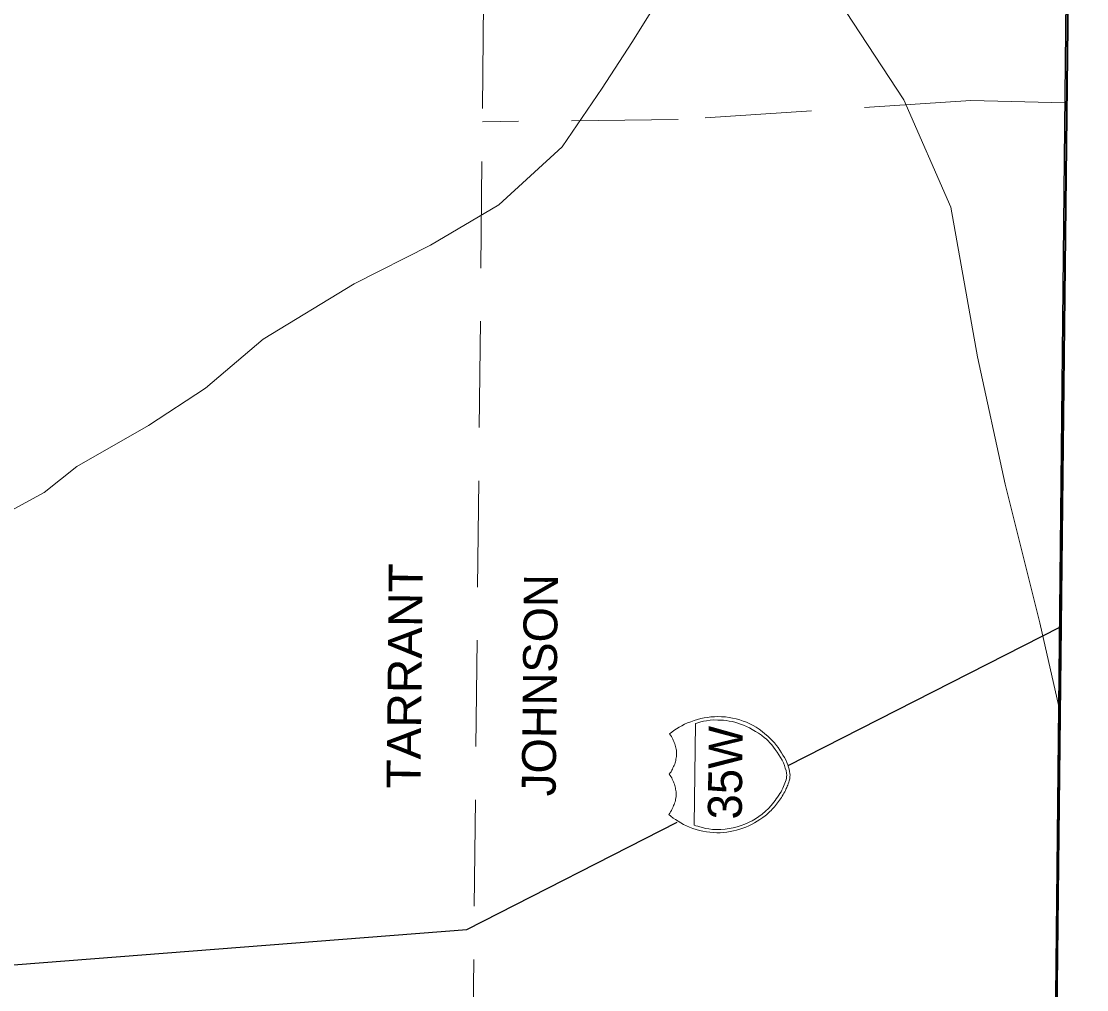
# Model space of a CAD drawing. Extents: x 2356576 to 2377878, y 6966390 to 6990634.
# Drawn here: x 2366013.1 to 2366226.3, y 6968926.1 to 6969120 of the extents above; entities that cross this region are included whole.
import ezdxf

# ---------------------------------------------------------------- set-up
doc = ezdxf.new("R2010")
doc.units = 0
doc.header["$LTSCALE"] = 7.1
doc.linetypes.add('MEDIUM_DASHED', pattern=[4.5, 3, -1.5])
doc.layers.add('19', color=7, linetype='Continuous', lineweight=13)
doc.layers.add('8', color=7, linetype='Continuous', lineweight=13)

msp = doc.modelspace()

# ---------------------------------------------------------------- linework, layer by layer
at = {"layer": '19', "lineweight": 35}
msp.add_line((2366217.375, 6968654.072), (2366226.339, 6969461.286), dxfattribs=at)
at = {"layer": '19', "linetype": 'MEDIUM_DASHED'}
msp.add_line((2366100.797, 6968655.28), (2366107.007, 6969254.676), dxfattribs=at)
at = {"layer": '19', "lineweight": 25}
msp.add_line((2366166.623, 6968971.011), (2366220.945, 6968998.678), dxfattribs=at)
for points in [[(2365597.072, 6968660.498), (2366217.375, 6968654.072), (2366223.585, 6969253.468), (2365603.282, 6969259.894)], [(2365867.731, 6968930.001), (2365932.844, 6968930.618), (2366007.222, 6968930.748), (2366102.256, 6968938.164), (2366144.393, 6968959.656)]]:
    msp.add_lwpolyline(points, dxfattribs=at)
at = {"layer": '19'}
for points in [[(2366057.323, 6969199.743), (2366069.126, 6969192.209), (2366091.194, 6969179.379), (2366116.101, 6969171.021), (2366135.168, 6969166.623), (2366152.425, 6969144.183), (2366165.834, 6969143.864), (2366178.148, 6969121.955), (2366189.725, 6969104.283), (2366199.135, 6969082.764), (2366204.465, 6969052.823), (2366210.021, 6969027.324), (2366216.934, 6968999.531), (2366220.78, 6968982.778)], [(2366155.514, 6969175.953), (2366151.383, 6969165.227), (2366148.79, 6969152.413), (2366143.811, 6969129.392), (2366135.33, 6969115.799), (2366129.355, 6969106.648), (2366121.344, 6969094.85), (2366108.711, 6969083.249), (2366095.035, 6969075.202), (2366079.714, 6969067.44), (2366061.538, 6969056.344), (2366050.004, 6969046.563), (2366038.586, 6969039.093), (2366024.252, 6969030.869), (2366017.685, 6969025.629), (2366000.609, 6969016.381)], [(2366143.422, 6968970.259), (2366143.545, 6968970.498), (2366143.668, 6968970.765), (2366143.762, 6968970.976), (2366143.885, 6968971.246), (2366143.947, 6968971.514), (2366144.038, 6968971.753), (2366144.1, 6968971.992), (2366144.135, 6968972.264), (2366144.198, 6968972.503), (2366144.261, 6968972.77), (2366144.263, 6968973.01), (2366144.266, 6968973.282), (2366144.268, 6968973.522), (2366144.271, 6968973.762), (2366144.214, 6968974.063), (2366144.156, 6968974.272), (2366144.127, 6968974.512), (2366144.069, 6968974.785), (2366143.984, 6968975.053), (2366143.927, 6968975.294), (2366143.809, 6968975.567), (2366143.72, 6968975.808), (2366143.602, 6968976.049), (2366143.485, 6968976.291), (2366143.367, 6968976.532), (2366143.222, 6968976.801), (2366143.045, 6968977.075), (2366142.868, 6968977.317), (2366143.291, 6968977.673), (2366143.743, 6968977.996), (2366144.226, 6968978.323), (2366144.769, 6968978.646), (2366145.284, 6968978.94), (2366145.856, 6968979.234), (2366146.458, 6968979.5), (2366147.093, 6968979.762), (2366147.756, 6968979.995), (2366148.418, 6968980.2), (2366149.108, 6968980.373), (2366149.769, 6968980.514), (2366150.462, 6968980.627), (2366151.151, 6968980.74), (2366151.844, 6968980.764), (2366152.532, 6968980.817), (2366153.284, 6968980.749), (2366154.031, 6968980.71), (2366154.782, 6968980.582), (2366155.473, 6968980.487), (2366156.192, 6968980.359), (2366156.909, 6968980.112), (2366157.595, 6968979.893), (2366158.252, 6968979.646), (2366158.909, 6968979.339), (2366159.566, 6968979.004), (2366160.162, 6968978.638), (2366160.79, 6968978.272), (2366161.386, 6968977.813), (2366161.949, 6968977.36), (2366162.516, 6968976.874), (2366163.05, 6968976.328), (2366163.466, 6968975.932), (2366163.85, 6968975.508), (2366164.237, 6968975.024), (2366164.592, 6968974.572), (2366164.915, 6968974.057), (2366165.242, 6968973.545), (2366165.537, 6968973.062), (2366165.832, 6968972.579), (2366166.095, 6968972.096), (2366166.302, 6968971.614), (2366166.505, 6968971.132), (2366166.68, 6968970.646), (2366166.795, 6968970.225), (2366166.883, 6968969.804), (2366166.939, 6968969.383), (2366166.963, 6968969.023)], [(2366166.963, 6968969.023), (2366166.932, 6968968.783), (2366166.93, 6968968.575), (2366166.896, 6968968.336), (2366166.834, 6968968.124), (2366166.771, 6968967.885), (2366166.709, 6968967.646), (2366166.618, 6968967.347), (2366166.523, 6968967.08), (2366166.4, 6968966.841), (2366166.309, 6968966.57), (2366166.154, 6968966.271), (2366166.032, 6968966.005), (2366165.908, 6968965.706), (2366165.758, 6968965.467), (2366165.575, 6968965.169), (2366165.42, 6968964.871), (2366165.237, 6968964.601), (2366165.054, 6968964.303), (2366164.843, 6968964.037), (2366164.66, 6968963.767), (2366164.478, 6968963.501), (2366164.235, 6968963.231), (2366164.052, 6968962.965), (2366163.838, 6968962.727), (2366163.595, 6968962.458), (2366163.384, 6968962.22), (2366163.17, 6968961.982), (2366162.928, 6968961.777), (2366162.685, 6968961.507), (2366162.475, 6968961.301), (2366162.233, 6968961.124), (2366161.991, 6968960.914), (2366161.507, 6968960.559), (2366160.931, 6968960.177), (2366160.388, 6968959.851), (2366159.844, 6968959.528), (2366159.273, 6968959.202), (2366158.698, 6968958.908), (2366158.127, 6968958.646), (2366157.525, 6968958.44), (2366156.922, 6968958.207), (2366156.288, 6968958.005), (2366155.627, 6968957.892), (2366154.997, 6968957.746), (2366154.336, 6968957.605), (2366153.703, 6968957.552), (2366152.983, 6968957.499), (2366152.29, 6968957.474), (2366151.603, 6968957.542), (2366150.912, 6968957.609), (2366150.225, 6968957.708), (2366149.534, 6968957.835), (2366148.876, 6968957.99), (2366148.19, 6968958.177), (2366147.532, 6968958.396), (2366146.874, 6968958.611), (2366146.245, 6968958.917), (2366145.648, 6968959.195), (2366145.083, 6968959.501), (2366144.574, 6968959.807), (2366144.038, 6968960.172), (2366143.561, 6968960.445), (2366143.117, 6968960.81), (2366142.7, 6968961.174), (2366142.883, 6968961.412), (2366143.066, 6968961.682), (2366143.216, 6968961.949), (2366143.339, 6968962.187), (2366143.462, 6968962.458), (2366143.584, 6968962.697), (2366143.679, 6968962.964), (2366143.801, 6968963.203), (2366143.864, 6968963.442), (2366143.954, 6968963.681), (2366144.017, 6968963.953), (2366144.052, 6968964.192), (2366144.115, 6968964.492), (2366144.177, 6968964.699), (2366144.179, 6968964.939), (2366144.182, 6968965.239), (2366144.185, 6968965.479), (2366144.187, 6968965.719), (2366144.13, 6968965.991), (2366144.073, 6968966.232), (2366144.043, 6968966.472), (2366143.986, 6968966.713), (2366143.901, 6968967.014), (2366143.843, 6968967.255), (2366143.726, 6968967.496), (2366143.636, 6968967.737), (2366143.519, 6968968.006), (2366143.402, 6968968.279), (2366143.284, 6968968.52), (2366143.139, 6968968.762), (2366142.961, 6968969.004), (2366142.784, 6968969.274), (2366142.967, 6968969.512), (2366143.149, 6968969.75), (2366143.3, 6968970.02), (2366143.422, 6968970.259)]]:
    msp.add_lwpolyline(points, dxfattribs=at)
at = {"layer": '19', "linetype": 'MEDIUM_DASHED'}
msp.add_lwpolyline([(2366222.033, 6969103.708), (2366203.137, 6969104.144), (2366144.562, 6969100.338), (2366105.403, 6969099.904)], dxfattribs=at)
at = {"layer": '19'}
msp.add_lwpolyline([(2366148.017, 6968979.364), (2366147.807, 6968959.053), (2366148.105, 6968958.93), (2366148.496, 6968958.806), (2366148.915, 6968958.682), (2366149.454, 6968958.556), (2366150.052, 6968958.398), (2366150.739, 6968958.271), (2366151.458, 6968958.203), (2366152.298, 6968958.194), (2366153.11, 6968958.186), (2366153.982, 6968958.237), (2366154.792, 6968958.349), (2366155.605, 6968958.52), (2366156.416, 6968958.724), (2366157.17, 6968958.956), (2366157.953, 6968959.216), (2366158.677, 6968959.568), (2366159.368, 6968959.921), (2366160.064, 6968960.306), (2366160.757, 6968960.779), (2366161.422, 6968961.252), (2366162.028, 6968961.814), (2366162.634, 6968962.408), (2366163.18, 6968963.002), (2366163.727, 6968963.656), (2366164.002, 6968963.954), (2366164.214, 6968964.311), (2366164.489, 6968964.641), (2366164.701, 6968965.026), (2366164.917, 6968965.356), (2366165.161, 6968965.714), (2366165.312, 6968966.072), (2366165.528, 6968966.43), (2366165.68, 6968966.788), (2366165.803, 6968967.115), (2366165.959, 6968967.473), (2366166.082, 6968967.772), (2366166.174, 6968968.131), (2366166.237, 6968968.431), (2366166.272, 6968968.73), (2366166.303, 6968969.03), (2366166.279, 6968969.45), (2366166.193, 6968969.963), (2366166.018, 6968970.445), (2366165.843, 6968970.987), (2366165.64, 6968971.501), (2366165.374, 6968972.044), (2366165.079, 6968972.555), (2366164.757, 6968973.098), (2366164.403, 6968973.642), (2366164.016, 6968974.158), (2366163.661, 6968974.642), (2366163.306, 6968975.093), (2366162.95, 6968975.549), (2366162.566, 6968975.941), (2366162.178, 6968976.305), (2366161.853, 6968976.548), (2366161.226, 6968977.035), (2366160.63, 6968977.433), (2366160.034, 6968977.827), (2366159.409, 6968978.194), (2366158.841, 6968978.532), (2366158.244, 6968978.806), (2366157.678, 6968979.052), (2366157.081, 6968979.27), (2366156.511, 6968979.484), (2366155.945, 6968979.67), (2366155.374, 6968979.796), (2366154.775, 6968979.894), (2366154.208, 6968979.988), (2366153.636, 6968980.054), (2366153.065, 6968980.092), (2366152.525, 6968980.097), (2366151.685, 6968980.106), (2366150.964, 6968980.053), (2366150.275, 6968979.941), (2366149.674, 6968979.855), (2366149.133, 6968979.712), (2366148.711, 6968979.565), (2366148.318, 6968979.449)], close=True, dxfattribs=at)
at = {"layer": '8', "lineweight": 35}
msp.add_line((2366217.375, 6968654.072), (2366226.339, 6969461.286), dxfattribs=at)
at = {"layer": '8', "linetype": 'MEDIUM_DASHED'}
msp.add_line((2366100.797, 6968655.28), (2366107.007, 6969254.676), dxfattribs=at)
at = {"layer": '8', "lineweight": 25}
msp.add_line((2366166.623, 6968971.011), (2366220.945, 6968998.678), dxfattribs=at)
for points in [[(2365597.072, 6968660.498), (2366217.375, 6968654.072), (2366223.585, 6969253.468), (2365603.282, 6969259.894)], [(2365867.731, 6968930.001), (2365932.844, 6968930.618), (2366007.222, 6968930.748), (2366102.256, 6968938.164), (2366144.393, 6968959.656)]]:
    msp.add_lwpolyline(points, dxfattribs=at)
at = {"layer": '8'}
for points in [[(2366057.323, 6969199.743), (2366069.126, 6969192.209), (2366091.194, 6969179.379), (2366116.101, 6969171.021), (2366135.168, 6969166.623), (2366152.425, 6969144.183), (2366165.834, 6969143.864), (2366178.148, 6969121.955), (2366189.725, 6969104.283), (2366199.135, 6969082.764), (2366204.465, 6969052.823), (2366210.021, 6969027.324), (2366216.934, 6968999.531), (2366220.78, 6968982.778)], [(2366155.514, 6969175.953), (2366151.383, 6969165.227), (2366148.79, 6969152.413), (2366143.811, 6969129.392), (2366135.33, 6969115.799), (2366129.355, 6969106.648), (2366121.344, 6969094.85), (2366108.711, 6969083.249), (2366095.035, 6969075.202), (2366079.714, 6969067.44), (2366061.538, 6969056.344), (2366050.004, 6969046.563), (2366038.586, 6969039.093), (2366024.252, 6969030.869), (2366017.685, 6969025.629), (2366000.609, 6969016.381)], [(2366143.422, 6968970.259), (2366143.545, 6968970.498), (2366143.668, 6968970.765), (2366143.762, 6968970.976), (2366143.885, 6968971.246), (2366143.947, 6968971.514), (2366144.038, 6968971.753), (2366144.1, 6968971.992), (2366144.135, 6968972.264), (2366144.198, 6968972.503), (2366144.261, 6968972.77), (2366144.263, 6968973.01), (2366144.266, 6968973.282), (2366144.268, 6968973.522), (2366144.271, 6968973.762), (2366144.214, 6968974.063), (2366144.156, 6968974.272), (2366144.127, 6968974.512), (2366144.069, 6968974.785), (2366143.984, 6968975.053), (2366143.927, 6968975.294), (2366143.809, 6968975.567), (2366143.72, 6968975.808), (2366143.602, 6968976.049), (2366143.485, 6968976.291), (2366143.367, 6968976.532), (2366143.222, 6968976.801), (2366143.045, 6968977.075), (2366142.868, 6968977.317), (2366143.291, 6968977.673), (2366143.743, 6968977.996), (2366144.226, 6968978.323), (2366144.769, 6968978.646), (2366145.284, 6968978.94), (2366145.856, 6968979.234), (2366146.458, 6968979.5), (2366147.093, 6968979.762), (2366147.756, 6968979.995), (2366148.418, 6968980.2), (2366149.108, 6968980.373), (2366149.769, 6968980.514), (2366150.462, 6968980.627), (2366151.151, 6968980.74), (2366151.844, 6968980.764), (2366152.532, 6968980.817), (2366153.284, 6968980.749), (2366154.031, 6968980.71), (2366154.782, 6968980.582), (2366155.473, 6968980.487), (2366156.192, 6968980.359), (2366156.909, 6968980.112), (2366157.595, 6968979.893), (2366158.252, 6968979.646), (2366158.909, 6968979.339), (2366159.566, 6968979.004), (2366160.162, 6968978.638), (2366160.79, 6968978.272), (2366161.386, 6968977.813), (2366161.949, 6968977.36), (2366162.516, 6968976.874), (2366163.05, 6968976.328), (2366163.466, 6968975.932), (2366163.85, 6968975.508), (2366164.237, 6968975.024), (2366164.592, 6968974.572), (2366164.915, 6968974.057), (2366165.242, 6968973.545), (2366165.537, 6968973.062), (2366165.832, 6968972.579), (2366166.095, 6968972.096), (2366166.302, 6968971.614), (2366166.505, 6968971.132), (2366166.68, 6968970.646), (2366166.795, 6968970.225), (2366166.883, 6968969.804), (2366166.939, 6968969.383), (2366166.963, 6968969.023)], [(2366166.963, 6968969.023), (2366166.932, 6968968.783), (2366166.93, 6968968.575), (2366166.896, 6968968.336), (2366166.834, 6968968.124), (2366166.771, 6968967.885), (2366166.709, 6968967.646), (2366166.618, 6968967.347), (2366166.523, 6968967.08), (2366166.4, 6968966.841), (2366166.309, 6968966.57), (2366166.154, 6968966.271), (2366166.032, 6968966.005), (2366165.908, 6968965.706), (2366165.758, 6968965.467), (2366165.575, 6968965.169), (2366165.42, 6968964.871), (2366165.237, 6968964.601), (2366165.054, 6968964.303), (2366164.843, 6968964.037), (2366164.66, 6968963.767), (2366164.478, 6968963.501), (2366164.235, 6968963.231), (2366164.052, 6968962.965), (2366163.838, 6968962.727), (2366163.595, 6968962.458), (2366163.384, 6968962.22), (2366163.17, 6968961.982), (2366162.928, 6968961.777), (2366162.685, 6968961.507), (2366162.475, 6968961.301), (2366162.233, 6968961.124), (2366161.991, 6968960.914), (2366161.507, 6968960.559), (2366160.931, 6968960.177), (2366160.388, 6968959.851), (2366159.844, 6968959.528), (2366159.273, 6968959.202), (2366158.698, 6968958.908), (2366158.127, 6968958.646), (2366157.525, 6968958.44), (2366156.922, 6968958.207), (2366156.288, 6968958.005), (2366155.627, 6968957.892), (2366154.997, 6968957.746), (2366154.336, 6968957.605), (2366153.703, 6968957.552), (2366152.983, 6968957.499), (2366152.29, 6968957.474), (2366151.603, 6968957.542), (2366150.912, 6968957.609), (2366150.225, 6968957.708), (2366149.534, 6968957.835), (2366148.876, 6968957.99), (2366148.19, 6968958.177), (2366147.532, 6968958.396), (2366146.874, 6968958.611), (2366146.245, 6968958.917), (2366145.648, 6968959.195), (2366145.083, 6968959.501), (2366144.574, 6968959.807), (2366144.038, 6968960.172), (2366143.561, 6968960.445), (2366143.117, 6968960.81), (2366142.7, 6968961.174), (2366142.883, 6968961.412), (2366143.066, 6968961.682), (2366143.216, 6968961.949), (2366143.339, 6968962.187), (2366143.462, 6968962.458), (2366143.584, 6968962.697), (2366143.679, 6968962.964), (2366143.801, 6968963.203), (2366143.864, 6968963.442), (2366143.954, 6968963.681), (2366144.017, 6968963.953), (2366144.052, 6968964.192), (2366144.115, 6968964.492), (2366144.177, 6968964.699), (2366144.179, 6968964.939), (2366144.182, 6968965.239), (2366144.185, 6968965.479), (2366144.187, 6968965.719), (2366144.13, 6968965.991), (2366144.073, 6968966.232), (2366144.043, 6968966.472), (2366143.986, 6968966.713), (2366143.901, 6968967.014), (2366143.843, 6968967.255), (2366143.726, 6968967.496), (2366143.636, 6968967.737), (2366143.519, 6968968.006), (2366143.402, 6968968.279), (2366143.284, 6968968.52), (2366143.139, 6968968.762), (2366142.961, 6968969.004), (2366142.784, 6968969.274), (2366142.967, 6968969.512), (2366143.149, 6968969.75), (2366143.3, 6968970.02), (2366143.422, 6968970.259)]]:
    msp.add_lwpolyline(points, dxfattribs=at)
at = {"layer": '8', "linetype": 'MEDIUM_DASHED'}
msp.add_lwpolyline([(2366222.033, 6969103.708), (2366203.137, 6969104.144), (2366144.562, 6969100.338), (2366105.403, 6969099.904)], dxfattribs=at)
at = {"layer": '8'}
msp.add_lwpolyline([(2366148.017, 6968979.364), (2366147.807, 6968959.053), (2366148.105, 6968958.93), (2366148.496, 6968958.806), (2366148.915, 6968958.682), (2366149.454, 6968958.556), (2366150.052, 6968958.398), (2366150.739, 6968958.271), (2366151.458, 6968958.203), (2366152.298, 6968958.194), (2366153.11, 6968958.186), (2366153.982, 6968958.237), (2366154.792, 6968958.349), (2366155.605, 6968958.52), (2366156.416, 6968958.724), (2366157.17, 6968958.956), (2366157.953, 6968959.216), (2366158.677, 6968959.568), (2366159.368, 6968959.921), (2366160.064, 6968960.306), (2366160.757, 6968960.779), (2366161.422, 6968961.252), (2366162.028, 6968961.814), (2366162.634, 6968962.408), (2366163.18, 6968963.002), (2366163.727, 6968963.656), (2366164.002, 6968963.954), (2366164.214, 6968964.311), (2366164.489, 6968964.641), (2366164.701, 6968965.026), (2366164.917, 6968965.356), (2366165.161, 6968965.714), (2366165.312, 6968966.072), (2366165.528, 6968966.43), (2366165.68, 6968966.788), (2366165.803, 6968967.115), (2366165.959, 6968967.473), (2366166.082, 6968967.772), (2366166.174, 6968968.131), (2366166.237, 6968968.431), (2366166.272, 6968968.73), (2366166.303, 6968969.03), (2366166.279, 6968969.45), (2366166.193, 6968969.963), (2366166.018, 6968970.445), (2366165.843, 6968970.987), (2366165.64, 6968971.501), (2366165.374, 6968972.044), (2366165.079, 6968972.555), (2366164.757, 6968973.098), (2366164.403, 6968973.642), (2366164.016, 6968974.158), (2366163.661, 6968974.642), (2366163.306, 6968975.093), (2366162.95, 6968975.549), (2366162.566, 6968975.941), (2366162.178, 6968976.305), (2366161.853, 6968976.548), (2366161.226, 6968977.035), (2366160.63, 6968977.433), (2366160.034, 6968977.827), (2366159.409, 6968978.194), (2366158.841, 6968978.532), (2366158.244, 6968978.806), (2366157.678, 6968979.052), (2366157.081, 6968979.27), (2366156.511, 6968979.484), (2366155.945, 6968979.67), (2366155.374, 6968979.796), (2366154.775, 6968979.894), (2366154.208, 6968979.988), (2366153.636, 6968980.054), (2366153.065, 6968980.092), (2366152.525, 6968980.097), (2366151.685, 6968980.106), (2366150.964, 6968980.053), (2366150.275, 6968979.941), (2366149.674, 6968979.855), (2366149.133, 6968979.712), (2366148.711, 6968979.565), (2366148.318, 6968979.449)], close=True, dxfattribs=at)

# ---------------------------------------------------------------- texts
at = {"layer": '19', "width": 1.05}
msp.add_text('TARRANT', height=6.798, rotation=89.406, dxfattribs=at).set_placement((2366093.007, 6968966.341))
at = {"layer": '19'}
for s, p in [('JOHNSON', (2366120.057, 6968964.801)), ('35W', (2366157.303, 6968960.155))]:
    msp.add_text(s, height=6.798, rotation=89.406, dxfattribs=at).set_placement(p)
at = {"layer": '8', "width": 1.05}
msp.add_text('TARRANT', height=6.798, rotation=89.406, dxfattribs=at).set_placement((2366093.007, 6968966.341))
at = {"layer": '8'}
for s, p in [('JOHNSON', (2366120.057, 6968964.801)), ('35W', (2366157.303, 6968960.155))]:
    msp.add_text(s, height=6.798, rotation=89.406, dxfattribs=at).set_placement(p)

doc.saveas('drawing.dxf')
